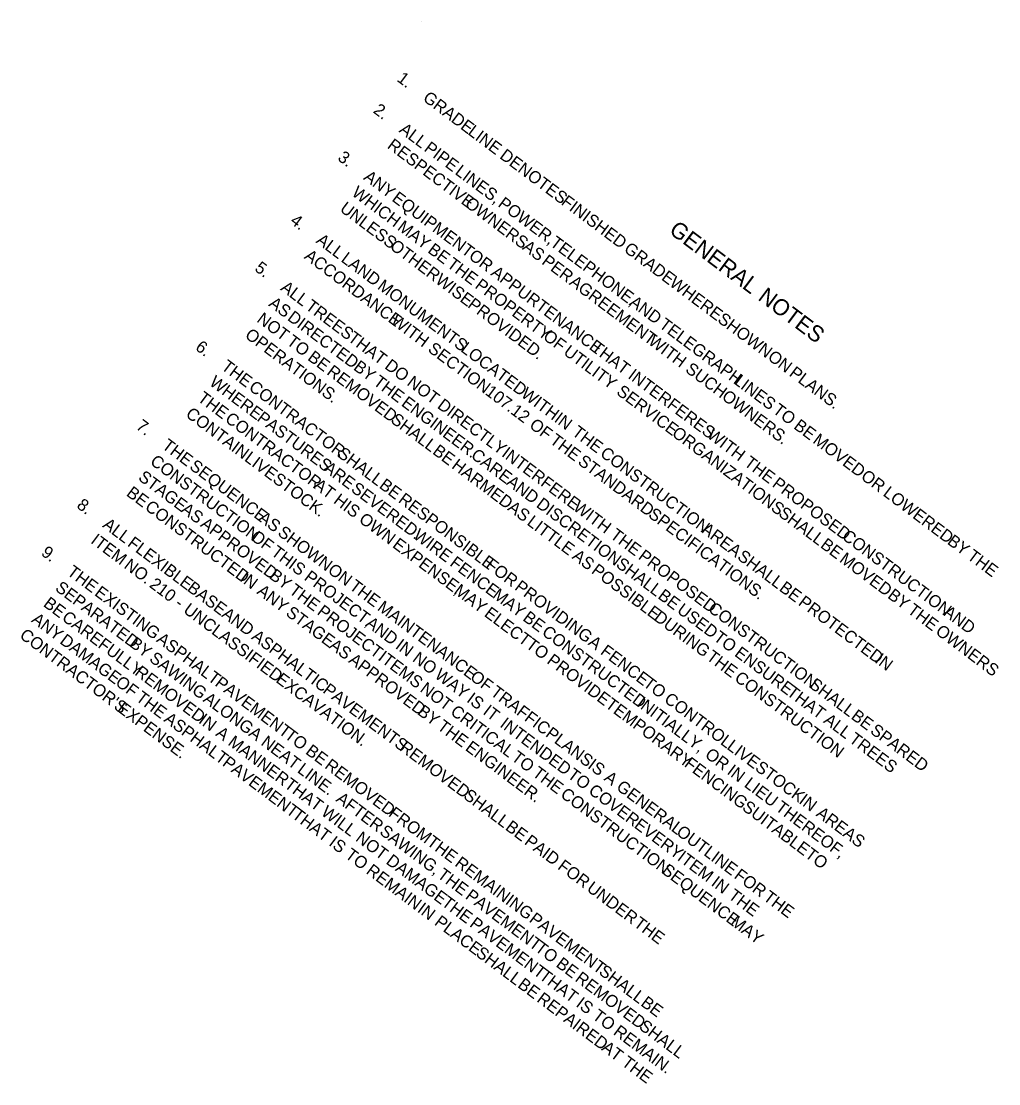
# Model space of a CAD drawing. Extents: x 626494 to 629419, y 365986 to 369334.
# Drawn here: x 627665.6 to 627670.42, y 368674.43 to 368679.68 of the extents above; entities that cross this region are included whole.
import ezdxf

# ---------------------------------------------------------------- set-up
doc = ezdxf.new("R2010")
doc.units = 0
doc.layers.add('Default', color=7, linetype='Continuous')
doc.layers.add('R_No Plot', color=7, linetype='Continuous')

msp = doc.modelspace()

# ---------------------------------------------------------------- linework, layer by layer
at = {"layer": 'R_No Plot'}
msp.add_line((627667.5735, 368679.6774), (627667.5735, 368679.6774), dxfattribs=at)

# ---------------------------------------------------------------- texts
at = {"layer": 'Default'}
for s, height, p in [('1.', 0.06, (627667.4468, 368679.3852)), ('GRADE', 0.06, (627667.5746, 368679.2892)), ('2.', 0.06, (627667.3297, 368679.2292)), ('ALL', 0.06, (627667.4575, 368679.1333)), (' LINE', 0.06, (627667.7788, 368679.1359)), ('RESPECTIVE', 0.06, (627667.399, 368679.0553)), (' PIPE', 0.06, (627667.5626, 368679.0544)), ('3.', 0.06, (627667.1541, 368678.9953)), (' DENOTES', 0.06, (627667.9358, 368679.018)), (' LINES,', 0.06, (627667.7154, 368678.9396)), ('ANY', 0.06, (627667.2819, 368678.8994)), ('WHICH', 0.06, (627667.2233, 368678.8214)), (' EQUIPMENT', 0.06, (627667.404, 368678.8077)), (' POWER,', 0.06, (627667.9274, 368678.7805)), (' FINISHED', 0.06, (627668.2395, 368678.7899)), ('UNLESS', 0.06, (627667.1648, 368678.7434)), (' OWNERS', 0.06, (627667.7641, 368678.7811)), ('4.', 0.06, (627666.9199, 368678.6835)), (' MAY', 0.06, (627667.4313, 368678.6652)), ('GENERAL', 0.08, (627668.7892, 368678.6352)), ('ALL', 0.06, (627667.0477, 368678.5875)), (' TELEPHONE,', 0.06, (627668.1846, 368678.5873)), ('ACCORDANCE', 0.06, (627666.9891, 368678.5095)), (' OTHERWISE', 0.06, (627667.3938, 368678.5715)), (' BE', 0.06, (627667.5808, 368678.553)), (' OR', 0.06, (627667.783, 368678.5231)), (' AS', 0.06, (627668.048, 368678.568)), (' GRADE', 0.06, (627668.5488, 368678.5577)), ('5.', 0.06, (627666.7443, 368678.4496)), (' LAND', 0.06, (627667.1527, 368678.5086)), (' THE', 0.06, (627667.6752, 368678.4821)), (' PER', 0.06, (627668.1433, 368678.4964)), (' APPURTENANCE', 0.06, (627667.8923, 368678.441)), ('ALL', 0.06, (627666.8721, 368678.3536)), (' MONUMENTS', 0.06, (627667.3325, 368678.3737)), (' PROPERTY', 0.06, (627667.8137, 368678.3781)), (' AGREEMENT', 0.06, (627668.2793, 368678.3943)), (' WHERE', 0.06, (627668.7736, 368678.3889)), (' NOTES', 0.08, (627669.2042, 368678.3236)), ('AS', 0.06, (627666.8135, 368678.2756)), (' TREES', 0.06, (627666.9771, 368678.2747)), (' PROVIDED.', 0.06, (627667.7779, 368678.2831)), (' AND', 0.06, (627668.5754, 368678.2939)), ('NOT', 0.06, (627666.755, 368678.1977)), (' DIRECTED', 0.06, (627666.8882, 368678.2196)), (' WITH', 0.06, (627667.3985, 368678.2022)), (' SHOWN', 0.06, (627669.0111, 368678.2105)), (' TELEGRAPH', 0.06, (627668.7223, 368678.1835)), ('OPERATIONS.', 0.06, (627666.6964, 368678.1197)), (' TO', 0.06, (627666.8842, 368678.1006)), (' THAT', 0.06, (627667.1863, 368678.1176)), (' OF', 0.06, (627668.1497, 368678.1258)), (' WITH', 0.06, (627668.669, 368678.1017)), ('6.', 0.06, (627666.4516, 368678.0597)), (' SECTION', 0.06, (627667.5814, 368678.0648)), (' LOCATED', 0.06, (627667.7435, 368678.065)), (' UTILITY', 0.06, (627668.2506, 368678.0501)), (' THAT', 0.06, (627668.3872, 368678.0694)), (' BE', 0.06, (627666.9879, 368678.0227)), (' ON', 0.06, (627669.2584, 368678.0248)), ('THE', 0.06, (627666.5793, 368677.9638)), (' REMOVED', 0.06, (627667.0823, 368677.9519)), (' BY', 0.06, (627667.214, 368677.9749)), (' DO', 0.06, (627667.3681, 368677.9811)), (' SUCH', 0.06, (627668.8519, 368677.9643)), (' PLANS.', 0.06, (627669.3649, 368677.9449)), ('WHERE', 0.06, (627666.5208, 368677.8858)), (' THE', 0.06, (627667.3119, 368677.9014)), (' NOT', 0.06, (627667.4781, 368677.8986)), (' INTERFERES', 0.06, (627668.569, 368677.9329)), (' LINES', 0.06, (627669.089, 368677.9082)), (' CONTRACTOR', 0.06, (627666.6973, 368677.8752)), (' 107.12', 0.06, (627667.8644, 368677.8523)), (' WITHIN', 0.06, (627668.0411, 368677.8416)), (' SERVICE', 0.06, (627668.512, 368677.8538)), ('THE', 0.06, (627666.4622, 368677.8078)), (' ENGINEER.', 0.06, (627667.4505, 368677.7973)), (' DIRECTLY', 0.06, (627667.6279, 368677.786)), (' OWNERS.', 0.06, (627669.0319, 368677.8292)), ('CONTAIN', 0.06, (627666.4037, 368677.7299)), (' TO', 0.06, (627669.2832, 368677.7624)), ('7.', 0.06, (627666.1588, 368677.6699)), (' CONTRACTOR', 0.06, (627666.5802, 368677.7193)), (' PASTURES', 0.06, (627666.7377, 368677.723)), (' SHALL', 0.06, (627667.3975, 368677.7152)), (' OF', 0.06, (627668.0821, 368677.6888)), (' BE', 0.06, (627669.3869, 368677.6845)), (' THE', 0.06, (627668.2927, 368677.6526)), (' ORGANIZATIONS', 0.06, (627668.7858, 368677.6482)), (' WITH', 0.06, (627668.9593, 368677.6398)), ('THE', 0.06, (627666.2866, 368677.5739)), (' THE', 0.06, (627668.183, 368677.6131)), (' MOVED', 0.06, (627669.4813, 368677.6137)), (' LIVESTOCK.', 0.06, (627666.676, 368677.5254)), (' SHALL', 0.06, (627667.1342, 368677.5472)), (' BE', 0.06, (627667.6045, 368677.5598)), (' CARE', 0.06, (627667.7937, 368677.5397)), (' INTERFERE', 0.06, (627667.9453, 368677.5477)), (' CONSTRUCTION', 0.06, (627668.4313, 368677.5486)), ('CONSTRUCTION', 0.06, (627666.2281, 368677.496)), (' SEQUENCE', 0.06, (627666.4046, 368677.4854)), (' ARE', 0.06, (627667.0659, 368677.4765)), (' HARMED', 0.06, (627667.6988, 368677.4889)), (' STANDARD', 0.06, (627668.3216, 368677.509)), (' THE', 0.06, (627669.1422, 368677.5025)), ('STAGE', 0.06, (627666.1695, 368677.418)), (' OR', 0.06, (627669.7185, 368677.4355)), (' AT', 0.06, (627667.0171, 368677.3912)), (' SEVERED.', 0.06, (627667.2019, 368677.3744)), (' BE', 0.06, (627667.3411, 368677.3918)), (' AND', 0.06, (627667.9693, 368677.4078)), (' PROPOSED', 0.06, (627669.2808, 368677.3984)), ('BE', 0.06, (627666.111, 368677.34)), (' HIS', 0.06, (627667.1158, 368677.3171)), (' RESPONSIBLE', 0.06, (627667.4355, 368677.3209)), (' LOWERED', 0.06, (627669.8278, 368677.3534)), ('8.', 0.06, (627665.8661, 368677.2801)), (' CONSTRUCTED', 0.06, (627666.1847, 368677.2847)), (' AS', 0.06, (627666.3633, 368677.2725)), (' AS', 0.06, (627667.9751, 368677.2815)), (' DISCRETION', 0.06, (627668.1162, 368677.2975)), (' WITH', 0.06, (627668.2983, 368677.2827)), (' AS', 0.06, (627666.7445, 368677.2301)), (' OWN', 0.06, (627667.2407, 368677.2233)), (' LITTLE', 0.06, (627668.0704, 368677.2099)), (' SPECIFICATIONS.', 0.06, (627668.669, 368677.2481)), (' SHALL', 0.06, (627669.3118, 368677.2532)), ('ALL', 0.06, (627665.9939, 368677.1841)), (' APPROVED', 0.06, (627666.4586, 368677.2009)), (' SHOWN', 0.06, (627666.8398, 368677.1586)), (' AREA', 0.06, (627668.9304, 368677.1738)), ('ITEM', 0.06, (627665.9353, 368677.1061)), (' FLEXIBLE', 0.06, (627666.0989, 368677.1052)), (' OF', 0.06, (627666.7066, 368677.1367)), (' EXPENSE,', 0.06, (627667.4067, 368677.0987)), (' WIRE', 0.06, (627667.5092, 368677.1437)), (' THE', 0.06, (627668.4812, 368677.1453)), (' BE', 0.06, (627669.5188, 368677.0978)), (' CONSTRUCTION', 0.06, (627669.625, 368677.14)), (' BY', 0.06, (627670.1451, 368677.1152)), ('9.', 0.06, (627665.6905, 368677.0462)), (' THIS', 0.06, (627666.8074, 368677.0609)), (' NO.', 0.06, (627666.0815, 368676.9964)), (' FENCE', 0.06, (627667.6897, 368677.0081)), (' FOR', 0.06, (627667.8659, 368676.9977)), (' AS', 0.06, (627668.2932, 368677.0426)), (' SHALL', 0.06, (627668.5096, 368677.0021)), (' PROPOSED', 0.06, (627668.6198, 368677.0412)), (' SHALL', 0.06, (627669.1084, 368677.0401)), (' MOVED', 0.06, (627669.6132, 368677.0269)), (' THE', 0.06, (627670.243, 368677.0417)), ('THE', 0.06, (627665.8183, 368676.9502)), (' BY', 0.06, (627666.7983, 368676.9459)), (' ON', 0.06, (627667.0871, 368676.9729)), (' POSSIBLE', 0.06, (627668.3885, 368676.9711)), (' 210', 0.06, (627666.2067, 368676.9024)), (' IN', 0.06, (627666.6531, 368676.933)), (' PROJECT,', 0.06, (627666.9709, 368676.9382)), (' THE', 0.06, (627667.1936, 368676.8929)), (' PROVIDING', 0.06, (627668.0096, 368676.8898)), ('SEPARATED', 0.06, (627665.7597, 368676.8722)), (' EXISTING', 0.06, (627665.9362, 368676.8616)), (' BASE', 0.06, (627666.3933, 368676.8842)), (' ANY', 0.06, (627666.7375, 368676.8696)), (' THE', 0.06, (627666.8963, 368676.8723)), (' MAY', 0.06, (627667.7099, 368676.871)), (' MAY', 0.06, (627667.9003, 368676.85)), (' BE', 0.06, (627668.7165, 368676.8467)), (' BE', 0.06, (627669.3154, 368676.8847)), (' BY', 0.06, (627669.8504, 368676.8488)), ('BE', 0.06, (627665.7012, 368676.7943)), (' -', 0.06, (627666.3326, 368676.8078)), (' MAINTENANCE', 0.06, (627667.3321, 368676.7889)), (' PROTECTED', 0.06, (627669.4098, 368676.8139)), (' CAREFULLY', 0.06, (627665.7749, 368676.7389)), (' UNCLASSIFIED', 0.06, (627666.3743, 368676.7765)), (' AND', 0.06, (627666.564, 368676.756)), (' STAGE', 0.06, (627666.8802, 368676.7625)), (' PROJECT.', 0.06, (627667.0348, 368676.7683)), (' ELECT', 0.06, (627667.8594, 368676.7587)), (' BE', 0.06, (627668.0498, 368676.7377)), (' DURING', 0.06, (627668.6969, 368676.7395)), (' USED', 0.06, (627668.8109, 368676.7758)), (' CONSTRUCTION', 0.06, (627668.964, 368676.7828)), (' THE', 0.06, (627669.9484, 368676.7752)), (' AND', 0.06, (627670.1241, 368676.7652)), ('ANY', 0.06, (627665.6426, 368676.7163)), (' AND', 0.06, (627667.2742, 368676.7104)), ("CONTRACTOR'S", 0.06, (627665.5841, 368676.6383)), (' ASPHALTIC', 0.06, (627666.7109, 368676.6457)), (' CONSTRUCTED', 0.06, (627668.1441, 368676.6669)), (' TO', 0.06, (627668.9912, 368676.6404)), (' OWNERS', 0.06, (627670.0869, 368676.6712)), (' DAMAGE', 0.06, (627665.7647, 368676.6246)), (' BY', 0.06, (627666.1082, 368676.6106)), (' ASPHALT', 0.06, (627666.2416, 368676.6323)), (' AS', 0.06, (627667.0946, 368676.6015)), (' IN', 0.06, (627667.4212, 368676.6001)), (' TO', 0.06, (627668.065, 368676.6043)), (' A', 0.06, (627668.3725, 368676.6173)), (' SAWING', 0.06, (627666.2061, 368676.537)), (' ITEMS', 0.06, (627667.3359, 368676.5422)), (' NO', 0.06, (627667.5056, 368676.5367)), (' PROVIDE', 0.06, (627668.1687, 368676.5265)), (' FENCE', 0.06, (627668.433, 368676.5719)), (' THE', 0.06, (627668.956, 368676.545)), (' ENSURE', 0.06, (627669.0949, 368676.5626)), (' IN', 0.06, (627669.7878, 368676.53)), (' REMOVED', 0.06, (627666.1345, 368676.4689)), (' APPROVED', 0.06, (627667.1899, 368676.5299)), (' EXCAVATION.', 0.06, (627666.8311, 368676.4335)), (' WAY', 0.06, (627667.6148, 368676.4547)), (' OF', 0.06, (627667.7896, 368676.4454)), (' TO', 0.06, (627668.6436, 368676.4137)), (' CONSTRUCTION', 0.06, (627669.0946, 368676.4409)), (' OF', 0.06, (627666.039, 368676.4187)), (' PAVEMENT', 0.06, (627666.5304, 368676.4155)), (' PAVEMENTS', 0.06, (627667.0629, 368676.3814)), (' NOT', 0.06, (627667.5427, 368676.3869)), (' TRAFFIC', 0.06, (627667.8904, 368676.3697)), (' THAT', 0.06, (627669.3524, 368676.3692)), (' SHALL', 0.06, (627669.4631, 368676.408)), (' THE', 0.06, (627666.1399, 368676.3429)), (' ALONG', 0.06, (627666.4721, 368676.3373)), (' IS', 0.06, (627667.7729, 368676.336)), (' TEMPORARY', 0.06, (627668.457, 368676.31)), (' INITIALLY,', 0.06, (627668.6124, 368676.3152)), (' CONTROL', 0.06, (627668.7473, 368676.3359)), (' EXPENSE.', 0.06, (627666.0483, 368676.2897)), (' BY', 0.06, (627667.5296, 368676.2748)), (' CRITICAL', 0.06, (627667.6925, 368676.2744)), (' IT', 0.06, (627667.8533, 368676.2756)), (' ASPHALT', 0.06, (627666.2785, 368676.2389)), (' IN', 0.06, (627666.4497, 368676.2322)), (' INTENDED', 0.06, (627667.937, 368676.2127)), (' ALL', 0.06, (627669.5342, 368676.2327)), (' BE', 0.06, (627669.6701, 368676.2526)), (' A', 0.06, (627666.5341, 368676.1689)), (' A', 0.06, (627666.6968, 368676.1686)), (' TO', 0.06, (627666.8738, 368676.1576)), (' THE', 0.06, (627667.6275, 368676.2013)), (' PLANS', 0.06, (627668.1621, 368676.1657)), (' SPARED', 0.06, (627669.7644, 368676.1818)), (' MANNER', 0.06, (627666.5946, 368676.1234)), (' NEAT', 0.06, (627666.7573, 368676.1232)), (' LIVESTOCK', 0.06, (627669.0571, 368676.1032)), (' TREES', 0.06, (627669.6599, 368676.1383)), (' BE', 0.06, (627666.9775, 368676.0797)), (' REMOVED', 0.06, (627667.4414, 368676.0972)), (' ENGINEER.', 0.06, (627667.7661, 368676.0973)), (' TO', 0.06, (627667.9933, 368676.0485)), (' OR', 0.06, (627668.9488, 368676.0626)), (' PAVEMENT', 0.06, (627666.5673, 368676.022)), (' REMOVED', 0.06, (627667.0719, 368676.0089)), (' IS', 0.06, (627668.3706, 368676.0091)), (' FENCING', 0.06, (627668.847, 368676.0172)), (' LINE.', 0.06, (627666.9371, 368675.9882)), (' THE', 0.06, (627668.097, 368675.9707)), (' TO', 0.06, (627668.2703, 368675.9625)), (' IN', 0.06, (627669.0581, 368675.9806)), (' THAT', 0.06, (627666.8727, 368675.9146)), (' A', 0.06, (627668.4509, 368675.9488)), (' GENERAL', 0.06, (627668.5114, 368675.9033)), (' LIEU', 0.06, (627669.1425, 368675.9172)), (' SHALL', 0.06, (627667.7566, 368675.8605)), (' CONSTRUCTION', 0.06, (627668.2356, 368675.8666)), (' COVER', 0.06, (627668.374, 368675.8846)), ('  AFTER', 0.06, (627667.11, 368675.8583)), (' SUITABLE', 0.06, (627669.1323, 368675.803)), (' THEREOF,', 0.06, (627669.2966, 368675.8015)), (' IN', 0.06, (627669.413, 368675.836)), (' THAT', 0.06, (627666.9107, 368675.7641)), (' WILL', 0.06, (627667.0546, 368675.778)), (' FROM', 0.06, (627667.3871, 368675.7722)), (' AREAS', 0.06, (627669.4974, 368675.7726)), (' BE', 0.06, (627667.9636, 368675.7051)), (' EVERY', 0.06, (627668.5994, 368675.7154)), (' NOT', 0.06, (627667.2247, 368675.6503)), (' SAWING,', 0.06, (627667.3427, 368675.6836)), (' THE', 0.06, (627667.5758, 368675.6305)), (' PAID', 0.06, (627668.0579, 368675.6342)), (' OUTLINE', 0.06, (627668.8074, 368675.6811)), (' IS', 0.06, (627667.0925, 368675.6276)), (' TO', 0.06, (627667.1728, 368675.5673)), (' DAMAGE', 0.06, (627667.3746, 368675.5377)), (' REMAINING', 0.06, (627667.7143, 368675.5265)), (' ITEM', 0.06, (627668.8128, 368675.5551)), (' TO', 0.06, (627669.4422, 368675.5702)), (' REMAIN', 0.06, (627667.2765, 368675.4894)), (' THE', 0.06, (627667.628, 368675.4694)), (' FOR', 0.06, (627668.2218, 368675.5112)), (' SEQUENCE', 0.06, (627668.7347, 368675.4918)), (' IN', 0.06, (627668.9795, 368675.4299)), (' FOR', 0.06, (627669.0928, 368675.4668)), (' UNDER', 0.06, (627668.3655, 368675.4033)), (' THE', 0.06, (627669.064, 368675.3665)), (' THE', 0.06, (627667.6489, 368675.3317)), (' PAVEMENT', 0.06, (627667.7665, 368675.3653)), (' THE', 0.06, (627669.2365, 368675.3589)), (' IN', 0.06, (627667.5293, 368675.2996)), (' PLACE', 0.06, (627667.6138, 368675.2362)), (' PAVEMENT', 0.06, (627667.7875, 368675.2277)), (' PAVEMENT', 0.06, (627668.0816, 368675.2507)), (' THE', 0.06, (627668.5972, 368675.2293)), (' MAY', 0.06, (627669.0746, 368675.2366)), (' TO', 0.06, (627668.11, 368675.1075)), (' SHALL', 0.06, (627667.8176, 368675.0831)), (' BE', 0.06, (627668.2137, 368675.0296)), (' THAT', 0.06, (627668.1309, 368674.9698)), (' REMOVED', 0.06, (627668.308, 368674.9587)), (' SHALL', 0.06, (627668.425, 368674.9928)), (' BE', 0.06, (627668.0246, 368674.9277)), (' REPAIRED', 0.06, (627668.119, 368674.8568)), (' IS', 0.06, (627668.3128, 368674.8333)), (' BE', 0.06, (627668.632, 368674.8374)), (' TO', 0.06, (627668.3931, 368674.773)), (' REMAIN.', 0.06, (627668.4968, 368674.6951)), (' SHALL', 0.06, (627668.6232, 368674.7221)), (' AT', 0.06, (627668.4388, 368674.6167)), (' THE', 0.06, (627668.5375, 368674.5426))]:
    msp.add_text(s, height=height, rotation=323.0976, dxfattribs=at).set_placement(p)

doc.saveas('drawing.dxf')
